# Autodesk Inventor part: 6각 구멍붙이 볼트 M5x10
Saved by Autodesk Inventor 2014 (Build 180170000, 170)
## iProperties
Created: 2026-07
Part Number: 6각 구멍붙이 볼트 M5x10
Material: 일반
Document SubType Name: Modeling
Designer: dg
Density: 1 g/cm^3
Appearance: 기본값
Author: dg
Author: jhkim
Description: 6각머리 태핑 나사
Creation Date: 2026-07-02
Sending System: Autodesk Inventor 2027
Preprocessor: ST-DEVELOPER v20.1
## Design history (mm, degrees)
node "6각 구멍붙이 볼트 M5x101"
body "Solid1"
node "기준1"
